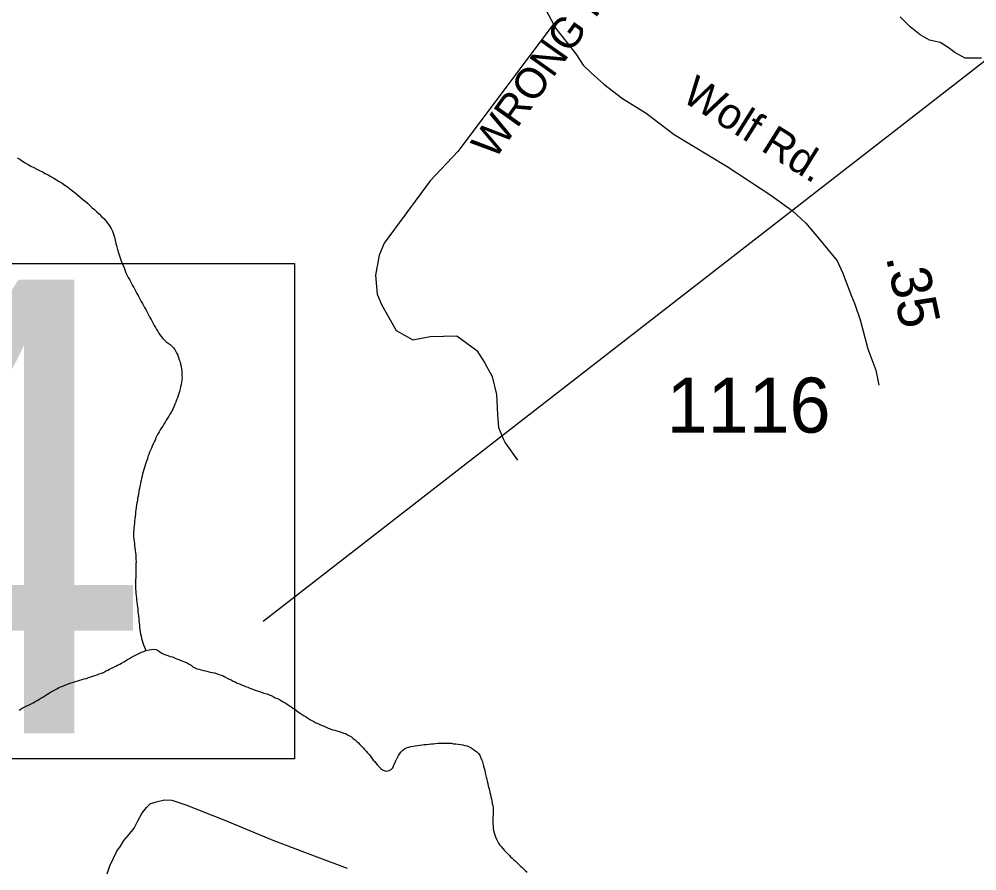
# Model space of a CAD drawing. Extents: x 1950930 to 2061844, y 904556 to 1017002.
# Drawn here: x 1983271 to 1986228, y 908118 to 910747 of the extents above; entities that cross this region are included whole.
import ezdxf

# ---------------------------------------------------------------- set-up
doc = ezdxf.new("R2010")
doc.units = 0
for name, color, linetype in [('Exist Hydrographic Creek Single Shore', 7, 'Continuous'), ('Exist Hydrographic Misc Water Feature', 7, 'Continuous'), ('Exist Road Non-System Type 51', 7, 'Continuous'), ('Exist Road Non-System Type 51 Label', 7, 'Continuous'), ('Exist Road Primary US Structure Standard Bridge CELL', 7, 'Continuous'), ('Exist Road Secondary Mileage Hundredths English Label', 7, 'Continuous'), ('Exist Road Secondary Type 51 Attributed', 7, 'Continuous'), ('Exist Road Secondary Type 51 Label', 7, 'Continuous'), ('Exist Road Secondary Type 51 Number Label', 7, 'Continuous')]:
    doc.layers.add(name, color=color, linetype=linetype)

msp = doc.modelspace()

# ---------------------------------------------------------------- linework, layer by layer
at = {"layer": 'Exist Hydrographic Creek Single Shore'}
for points in [[(1986242.9, 910626.3), (1986191.7, 910626.3), (1986160.6, 910643.4), (1986139.4, 910658.9), (1986115, 910674.4), (1986082.4, 910681.7), (1986052.6, 910698.8), (1986022.6, 910722.6), (1985991, 910754.2)], [(1983265, 910319.1), (1983273.4, 910314.2), (1983282, 910308.7), (1983290.4, 910303.8), (1983298.8, 910298.5), (1983307.8, 910293.5), (1983316.4, 910289.4), (1983325.5, 910284.3), (1983334.1, 910279.7), (1983343.5, 910275.5), (1983352.1, 910270.5), (1983361.1, 910266.3), (1983369.6, 910261)], [(1983369.6, 910261), (1983378.6, 910255.9), (1983387, 910250.6), (1983395.4, 910245.7), (1983404, 910240.8), (1983412, 910234.6), (1983420.4, 910228.9), (1983428.2, 910222.8), (1983436.2, 910217.2), (1983444, 910210.3), (1983452, 910204.6), (1983459.4, 910197.8), (1983467.2, 910191.7), (1983475.2, 910185.3), (1983482.5, 910178.4), (1983489.7, 910171.7), (1983497.1, 910164.9), (1983504.3, 910158.9), (1983511.7, 910152.1), (1983518.6, 910145.8), (1983525.4, 910138.2), (1983532.4, 910131.5), (1983538.7, 910124.1), (1983544.7, 910116.2), (1983550.4, 910108.9), (1983555.3, 910100.4), (1983559.4, 910092.1), (1983562.9, 910083), (1983565.8, 910074), (1983568, 910064.4), (1983570.1, 910054.4), (1983572.8, 910044.2), (1983574.6, 910035.4), (1983578.1, 910025.6), (1983581.2, 910016.5), (1983584.5, 910007.1), (1983587.7, 909997.3), (1983591.8, 909988.1), (1983595.3, 909979.1), (1983598.6, 909970.1)], [(1983598.6, 909970.1), (1983601.9, 909961.9), (1983605, 909955.3), (1983608.2, 909949.1), (1983611.9, 909943.2), (1983615.2, 909936.7), (1983618.5, 909930.9), (1983621.6, 909924.4), (1983625.3, 909918.5), (1983628.3, 909912), (1983631.6, 909906.2), (1983634.9, 909900.4), (1983638.6, 909893.8), (1983641.5, 909888.1), (1983644.9, 909881.4), (1983648.2, 909875.3), (1983651.9, 909869), (1983655, 909862.8), (1983658.3, 909857.1), (1983662, 909850.4), (1983665.2, 909844.7), (1983668.3, 909838.1), (1983671.6, 909832.3), (1983674.9, 909825.7), (1983678.6, 909819.9), (1983681.6, 909813.3), (1983684.9, 909807.6), (1983688.2, 909801.8), (1983691.9, 909795.2), (1983695.4, 909788.9), (1983699.3, 909783.5), (1983703, 909777.6), (1983706.7, 909771.8), (1983710.8, 909766), (1983715.5, 909760.7), (1983720.2, 909756), (1983725.5, 909750.7), (1983731.3, 909746.6), (1983737.4, 909742.4), (1983742.5, 909737.1), (1983747.7, 909732.3), (1983751.6, 909727.3), (1983754.8, 909721.5), (1983757.9, 909714.9), (1983760.8, 909709.3), (1983763.5, 909702.3), (1983765.7, 909695.1), (1983768, 909688.7), (1983769.8, 909681.9), (1983771.5, 909674.3), (1983772.9, 909666.8), (1983773.5, 909660.3), (1983773.9, 909652.9), (1983774.1, 909646.3), (1983774.3, 909639.7), (1983773.7, 909633.4), (1983772.9, 909625.8), (1983771.7, 909619.4), (1983770, 909612.1), (1983768.6, 909605.4), (1983766.5, 909597.9), (1983764.5, 909591.8), (1983762.2, 909585.2), (1983760.2, 909577.8), (1983757.3, 909571.4), (1983755.1, 909564.8), (1983751.8, 909558.4), (1983749.5, 909551.9), (1983746.6, 909545.4), (1983743.6, 909539.8), (1983740.3, 909532.9), (1983736.8, 909527.4), (1983733.3, 909521), (1983729.6, 909515.1), (1983725.7, 909508.8), (1983722.2, 909503.3), (1983718.4, 909497.3), (1983714.7, 909491), (1983710.8, 909485.1), (1983706.9, 909479.6), (1983703.6, 909473.2), (1983700.1, 909467.6), (1983696.8, 909460.8), (1983693.7, 909454.4), (1983690.9, 909447.9), (1983687.8, 909442.3), (1983685.5, 909435.8), (1983682.3, 909429.4), (1983680, 909422.8), (1983677.1, 909416.3), (1983674.3, 909409.9), (1983672, 909403.3), (1983669.1, 909396.9), (1983667.3, 909390.3), (1983664.8, 909382.9), (1983662.4, 909376.4), (1983660.1, 909369.8), (1983658.1, 909363.2), (1983656.2, 909356.7), (1983654.4, 909349.2)], [(1983654.4, 909349.2), (1983652.1, 909343), (1983651.1, 909336.3), (1983649.5, 909328.9), (1983647.8, 909322.5), (1983646.4, 909315.9), (1983645.1, 909308.4), (1983643.7, 909302.1), (1983642.1, 909295.5), (1983640.8, 909288.3), (1983639.8, 909281.6), (1983638.6, 909274.1), (1983637.1, 909267.8), (1983636.3, 909260.2), (1983634.7, 909253.9), (1983633.9, 909246.4), (1983632.8, 909240.1), (1983631.6, 909232.5), (1983631, 909226.2), (1983630.2, 909218.6), (1983629.6, 909212.1), (1983628.7, 909204.5), (1983627.9, 909198.2), (1983627.1, 909190.6), (1983626.5, 909184.2), (1983625.7, 909177), (1983625.1, 909170.2), (1983624.6, 909163), (1983624.8, 909156.4), (1983624.8, 909149.2), (1983625.5, 909142.6), (1983626.5, 909135.1), (1983627.1, 909128.6), (1983627.9, 909121.1), (1983628.9, 909114.4), (1983629.8, 909107), (1983630.4, 909100.5), (1983631.4, 909093), (1983631.8, 909086.4), (1983632, 909079), (1983632.2, 909072.6), (1983631.8, 909065.3), (1983632, 909058.7), (1983631.6, 909051.1), (1983631.8, 909044.6), (1983631.4, 909037.4), (1983631.2, 909030.9), (1983631.2, 909023.2), (1983630.8, 909016), (1983630.6, 909009.5), (1983630.6, 909002.1), (1983630.8, 908995.7), (1983630.8, 908988), (1983631.4, 908981.3), (1983631.8, 908973.9), (1983632.6, 908967.8), (1983633.5, 908960), (1983633.9, 908953.3), (1983635.1, 908947.1), (1983635.9, 908939.7), (1983636.9, 908933), (1983637.4, 908925.7), (1983638, 908919.1), (1983639, 908911.6), (1983639.6, 908905), (1983640.4, 908897.6), (1983641, 908891), (1983641.5, 908883.6), (1983642.5, 908877), (1983642.9, 908869.7), (1983643.9, 908863), (1983644.9, 908855.9), (1983646.4, 908849.3), (1983647.8, 908842.5), (1983649, 908835), (1983651.1, 908828.7), (1983653.3, 908821.8), (1983655.6, 908815.3), (1983658.3, 908808.9), (1983663, 908798)], [(1983663, 908798), (1983673, 908800.2), (1983680, 908801.5), (1983687, 908802.4), (1983693.5, 908801.5), (1983700.3, 908798), (1983706, 908793.9), (1983711.8, 908790.2), (1983717.9, 908786.8), (1983724.5, 908785), (1983730.9, 908782.4), (1983737.6, 908780.2), (1983744.6, 908778.3), (1983751.4, 908775.7), (1983757.7, 908773), (1983764.1, 908770.4), (1983770.4, 908767.9), (1983777.2, 908765.2), (1983783.6, 908762.6), (1983789.9, 908760), (1983796.3, 908756.6), (1983802, 908752.5), (1983807.5, 908748), (1983813.3, 908744.7), (1983820.1, 908742), (1983826.6, 908740.3), (1983833.6, 908738.3), (1983840.6, 908736.9), (1983847.1, 908735.2), (1983853.9, 908733.2), (1983860.9, 908731.4), (1983867.4, 908730.3), (1983874, 908729), (1983881, 908727.1), (1983887.7, 908724.5), (1983894.7, 908722.6), (1983901.1, 908720), (1983906.8, 908716.7), (1983913.1, 908713.3), (1983919.3, 908709.9), (1983925.7, 908707.4), (1983932.4, 908703.9), (1983938.8, 908701.3), (1983944.9, 908697.9), (1983951.3, 908695.3), (1983957.6, 908692.7), (1983964, 908690.2), (1983970.4, 908687.6), (1983977.1, 908684.9), (1983983.5, 908682.3), (1983990.2, 908679.6), (1983997.2, 908677), (1984003.2, 908675.3), (1984009.9, 908672.6), (1984016.5, 908670.8), (1984023.3, 908668.1), (1984029.6, 908665.5), (1984036.6, 908664.1), (1984042.9, 908661.1), (1984049.3, 908658.9), (1984056.1, 908656.2), (1984062.2, 908652.4), (1984068.6, 908649.9), (1984074.9, 908646.9), (1984081.1, 908643.1), (1984087, 908639.8), (1984092.8, 908636.4), (1984099.3, 908632.2), (1984105.1, 908628.9), (1984110.8, 908624.4), (1984116.4, 908620.3), (1984122.3, 908616.9), (1984128, 908612.8), (1984133.6, 908608.3), (1984139.3, 908605.1), (1984145.1, 908601), (1984151.2, 908596.8), (1984157, 908593.5), (1984162.7, 908589), (1984168.4, 908585.6), (1984174.6, 908582.2), (1984180.9, 908578.8), (1984187.1, 908575.4), (1984193.5, 908572.9), (1984200.2, 908569.4), (1984206.6, 908566.8), (1984212.9, 908564.3), (1984219.3, 908561.7), (1984225.6, 908559), (1984232, 908556.5), (1984238.8, 908553.8), (1984245.7, 908551.9), (1984252.3, 908550.1), (1984259.1, 908547.8), (1984265.6, 908546.1), (1984272.4, 908543.4), (1984278.8, 908541.6), (1984285.5, 908538.2), (1984291.3, 908534.8), (1984297.2, 908531.5)], [(1983271.1, 908614.1), (1983277.3, 908618.1), (1983283.2, 908621.2), (1983289.4, 908624.3), (1983295.3, 908627.4), (1983301.9, 908630.5), (1983308.2, 908633.6), (1983314.4, 908637.1), (1983320.5, 908640.6), (1983326.7, 908644.2), (1983332.6, 908647.3), (1983338.8, 908651.3), (1983344.5, 908654.5), (1983350.7, 908658.4), (1983356.8, 908662.4), (1983362.4, 908665.5), (1983368.7, 908669.4), (1983374.7, 908672.6), (1983380.8, 908675.7), (1983387.4, 908679.6), (1983393.3, 908682.8), (1983399.5, 908685.8), (1983405.9, 908688.6), (1983412.2, 908691.7), (1983419, 908693.8), (1983425.7, 908696.1), (1983432.1, 908698.4), (1983438.9, 908701), (1983445.6, 908702.5), (1983452.2, 908704.6), (1983459, 908706.9), (1983465.7, 908708.3), (1983472.5, 908710.9), (1983479.1, 908712.3), (1983485.8, 908714.6), (1983492.6, 908716.8), (1983499.4, 908719.4), (1983505.5, 908720.9), (1983512.3, 908723.1), (1983518.8, 908726.1), (1983525.6, 908728.4), (1983531.8, 908730.7), (1983537.9, 908734.2), (1983544.9, 908737.2), (1983550.8, 908740.4), (1983557, 908743.5), (1983563.3, 908746.5), (1983569.5, 908749.7), (1983575.4, 908752.9), (1983582, 908756), (1983587.9, 908759.1), (1983594.3, 908763.4), (1983600.2, 908766.5), (1983606, 908770.5), (1983612.1, 908773.7), (1983618.3, 908777.6)], [(1984297.2, 908531.5), (1984302.7, 908527), (1984308.5, 908522.9), (1984313.6, 908517.7), (1984318.7, 908512.9), (1984323.5, 908508.1), (1984328.4, 908502.8), (1984333.1, 908497.7), (1984337.8, 908492.9), (1984342.9, 908487.7), (1984347.2, 908482.9), (1984351.8, 908477), (1984356.1, 908471.9), (1984360.6, 908465.9), (1984364.3, 908460.1), (1984369, 908455.3), (1984374.1, 908450), (1984378.2, 908444.2), (1984383.3, 908439.3), (1984388.5, 908434), (1984393.6, 908430), (1984399.9, 908426.7), (1984406.5, 908425.6), (1984413.3, 908427.9), (1984419.8, 908431.3), (1984424.8, 908435.8), (1984427.2, 908442.3), (1984429.9, 908448.8), (1984432.8, 908455.7), (1984436, 908462.1), (1984439.5, 908467.7), (1984442.6, 908474.1), (1984446.7, 908480), (1984450.6, 908485.5), (1984455.5, 908490.4), (1984461.3, 908494.4), (1984467.4, 908497.5), (1984474.2, 908499.8), (1984480.9, 908502), (1984487.5, 908503.5), (1984494.5, 908504.4), (1984501.4, 908505), (1984508.4, 908506.3), (1984515.4, 908507.2), (1984522.2, 908507.9), (1984529.1, 908508.5), (1984536.5, 908509.4), (1984543.1, 908510), (1984549.8, 908510.5), (1984557.2, 908511), (1984564.6, 908512), (1984571.4, 908511.8), (1984578.1, 908512.4), (1984584.9, 908512.2), (1984592.3, 908512.3), (1984599.5, 908512), (1984606.2, 908511.8), (1984612.8, 908510.7), (1984620, 908510), (1984626.9, 908509), (1984633.9, 908508), (1984641.1, 908506.8), (1984647.6, 908505.1), (1984654.2, 908503.7), (1984661, 908501), (1984667.1, 908497.6), (1984672.9, 908493.9), (1984678.6, 908489.8), (1984683.9, 908485.7), (1984689.3, 908480.4), (1984693.6, 908475), (1984696.2, 908468.8), (1984699.1, 908462.3), (1984701.4, 908455.5), (1984703.2, 908449.1), (1984705.1, 908441.5), (1984706.9, 908435.2), (1984708.8, 908428.4), (1984710.2, 908422), (1984711.6, 908415.4), (1984713.3, 908407.8), (1984715.1, 908401), (1984716.7, 908394.7), (1984718.6, 908387.9), (1984719.8, 908380.8), (1984721.7, 908374.1), (1984723.1, 908367.3), (1984725, 908360.1), (1984726.4, 908353.5), (1984727.8, 908346.8), (1984729.3, 908340), (1984731.1, 908332.8), (1984732.1, 908326.2), (1984733.6, 908319.5), (1984734.4, 908312), (1984735, 908305.5), (1984735, 908298.2), (1984734.4, 908291.7), (1984733.6, 908284.1), (1984733.8, 908277.7)], [(1984733.8, 908277.7), (1984733.8, 908270.3), (1984734, 908263.8), (1984734.4, 908256.5), (1984735, 908249.9), (1984736, 908242.4), (1984737.5, 908235.8), (1984739.7, 908229.3), (1984742, 908222.8), (1984744.6, 908216), (1984747.9, 908210.1), (1984751.6, 908203.6), (1984755.7, 908197.6), (1984760, 908192.9), (1984764.5, 908187), (1984768.8, 908181.8), (1984774, 908177), (1984779.1, 908171.8), (1984783.8, 908167), (1984788.7, 908161.7), (1984793.4, 908157), (1984798.8, 908152.5), (1984803.9, 908147.7), (1984808.6, 908142.6), (1984813.7, 908137.6), (1984818.7, 908132.4), (1984824, 908128.4), (1984829.1, 908123.2), (1984834.2, 908118.4), (1984839.4, 908113.9)]]:
    msp.add_lwpolyline(points, dxfattribs=at)
at = {"layer": 'Exist Hydrographic Misc Water Feature'}
msp.add_lwpolyline([(1983618.3, 908777.6), (1983624.2, 908780.8), (1983630.4, 908783.9), (1983636.7, 908786.9), (1983643.3, 908790), (1983649.2, 908793.2), (1983656, 908795.3), (1983663, 908798)], dxfattribs=at)
at = {"layer": 'Exist Road Non-System Type 51'}
for points in [[(1984920.5, 910730.2), (1984625.4, 910338.5), (1984539.9, 910247.8), (1984398.4, 910055.5), (1984382.4, 910018.1), (1984371.8, 909956.8), (1984377, 909898), (1984390.4, 909866), (1984435.8, 909785.9), (1984486.5, 909756.6), (1984539.9, 909767.2), (1984622.6, 909769.9), (1984684, 909724.5), (1984708.1, 909687.1), (1984732.1, 909644.4), (1984745.5, 909588.4), (1984748.1, 909526.9), (1984750.8, 909486.9), (1984766.8, 909449.6), (1984772.1, 909438.9), (1984809.5, 909385.4)], [(1983542.8, 908109.1), (1983551.8, 908133.9), (1983562.9, 908157.4), (1983572.9, 908179.4), (1983583.9, 908194.4), (1983594.9, 908211.5), (1983608.9, 908228.5), (1983626, 908249.5), (1983638, 908272.6), (1983650, 908295.6), (1983665, 908313.6), (1983676, 908324.6), (1983694, 908331.6), (1983720, 908337.6), (1983743, 908336.6), (1983786.1, 908321.6), (1983908.2, 908273.6), (1984054.4, 908212.5), (1984190.5, 908161.4), (1984283.6, 908126.4)]]:
    msp.add_lwpolyline(points, dxfattribs=at)
at = {"layer": 'Exist Road Secondary Mileage Hundredths English Label'}
msp.add_line((1988804.5, 912600.2), (1984025, 908887.3), dxfattribs=at)
msp.add_lwpolyline([(1981545.1, 909992.8), (1984121.6, 909992.8), (1984121.6, 908463.6), (1981545.1, 908463.6)], close=True, dxfattribs=at)
at = {"layer": 'Exist Road Secondary Type 51 Attributed'}
msp.add_lwpolyline([(1984898.2, 910773.1), (1984928.6, 910718.4), (1984990.1, 910640.2), (1985012.8, 910605.2), (1985037.1, 910580.9), (1985076.6, 910546), (1985134.3, 910501.9), (1985207.2, 910456.3), (1985293.7, 910391), (1985457.7, 910292.2), (1985592.1, 910203.3), (1985658.9, 910154.7), (1985699.9, 910116.7), (1985739.3, 910071.1), (1985768.2, 910036.1), (1985797, 910001.2), (1985813.7, 909964.7), (1985841.1, 909891.8), (1985851.6, 909866.8), (1985868.1, 909818.9), (1985891.2, 909729.8), (1985915.9, 909663.8), (1985925.8, 909617.6)], dxfattribs=at)

# ---------------------------------------------------------------- texts
at = {"layer": 'Exist Road Non-System Type 51 Label'}
msp.add_text('  WRONG RD', height=95, rotation=54.5844, dxfattribs=at).set_placement((1984697.9, 910252.3))
at = {"layer": 'Exist Road Primary US Structure Standard Bridge CELL'}
msp.add_text('.35', height=125, rotation=282.0848, dxfattribs=at).set_placement((1985946.8, 910012.6))
at = {"layer": 'Exist Road Secondary Mileage Hundredths English Label'}
msp.add_text('14', height=1400, dxfattribs=at).set_placement((1981595.2, 908542.7))
at = {"layer": 'Exist Road Secondary Type 51 Label'}
msp.add_text('Wolf Rd.', height=95, rotation=327.8882, dxfattribs=at).set_placement((1985312.7, 910497))
at = {"layer": 'Exist Road Secondary Type 51 Number Label'}
msp.add_text('1116', height=170, dxfattribs=at).set_placement((1985270.5, 909470.6))

doc.saveas('drawing.dxf')
